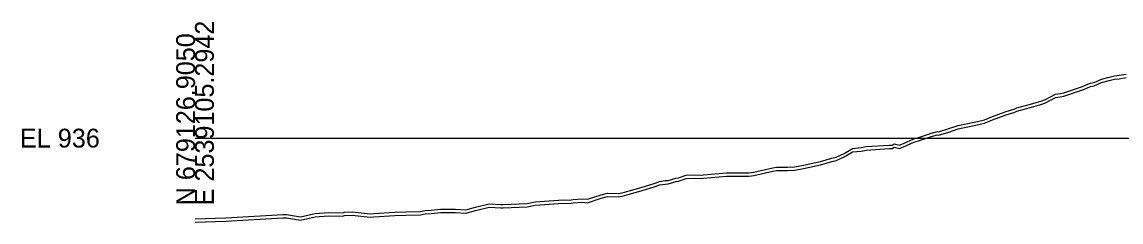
# Model space of a CAD drawing. Extents: x -26 to 2539581, y -16 to 679563.
# Drawn here: x -25.7 to 137.5, y 4987.5 to 5017.3 of the extents above; entities that cross this region are included whole.
import ezdxf

# ---------------------------------------------------------------- set-up
doc = ezdxf.new("R2010")
doc.units = 0
for name, color, linetype in [('DESIGN - SHEET - Light Grid', 7, 'Continuous'), ('SURVEY - GROUND - Bottom of Topsoil Layer', 7, 'Continuous'), ('SURVEY - GROUND - Top of Ground', 7, 'Continuous')]:
    doc.layers.add(name, color=color, linetype=linetype)

msp = doc.modelspace()

# ---------------------------------------------------------------- linework, layer by layer
at = {"layer": 'DESIGN - SHEET - Light Grid'}
msp.add_line((0, 5000), (150, 5000), dxfattribs=at)
at = {"layer": 'SURVEY - GROUND - Bottom of Topsoil Layer'}
for p, q in [((133.52, 5007.79), (134.6, 5008.28)), ((134.6, 5008.28), (135.75, 5008.59)), ((135.75, 5008.59), (136.54, 5008.76)), ((136.54, 5008.76), (137.22, 5008.85)), ((137.22, 5008.85), (138.26, 5009)), ((128.98, 5006.24), (131.76, 5007.18)), ((131.76, 5007.18), (132.08, 5007.31)), ((132.08, 5007.31), (132.96, 5007.68)), ((132.96, 5007.68), (133.52, 5007.79)), ((124.06, 5004.54), (124.52, 5004.7)), ((124.52, 5004.7), (125.57, 5005.02)), ((125.57, 5005.02), (126.27, 5005.23)), ((126.27, 5005.23), (127.02, 5005.67)), ((127.02, 5005.67), (127.74, 5006.04)), ((127.74, 5006.04), (128.43, 5006.14)), ((128.43, 5006.14), (128.98, 5006.24)), ((118.42, 5002.7), (120.27, 5003.41)), ((120.27, 5003.41), (121.73, 5003.88)), ((121.73, 5003.88), (122.04, 5004)), ((122.04, 5004), (123.32, 5004.37)), ((123.32, 5004.37), (124.06, 5004.54)), ((113.33, 5001.36), (113.98, 5001.51)), ((113.98, 5001.51), (116.18, 5001.99)), ((116.18, 5001.99), (117.2, 5002.21)), ((117.2, 5002.21), (118.07, 5002.57)), ((118.07, 5002.57), (118.42, 5002.7)), ((107.4, 4999.58), (109.5, 5000.3)), ((109.5, 5000.3), (110.24, 5000.51)), ((110.24, 5000.51), (110.4, 5000.42)), ((110.4, 5000.42), (111.91, 5000.91)), ((111.91, 5000.91), (113.33, 5001.36)), ((98.88, 4998.08), (99.65, 4998.23)), ((99.65, 4998.23), (103.08, 4998.45)), ((103.08, 4998.45), (103.56, 4998.46)), ((103.56, 4998.46), (103.78, 4998.65)), ((103.78, 4998.65), (104.53, 4998.47)), ((104.53, 4998.47), (105.17, 4998.68)), ((105.17, 4998.68), (106.73, 4999.4)), ((106.73, 4999.4), (107.4, 4999.58)), ((94.57, 4996.54), (95.18, 4996.67)), ((95.18, 4996.67), (96.37, 4997.22)), ((96.37, 4997.22), (97.61, 4997.97)), ((97.61, 4997.97), (98.88, 4998.08)), ((82.95, 4994.43), (85.77, 4995.08)), ((85.77, 4995.08), (86.32, 4995.19)), ((86.32, 4995.19), (87.97, 4995.2)), ((87.97, 4995.2), (88.4, 4995.21)), ((88.4, 4995.21), (88.78, 4995.17)), ((88.78, 4995.17), (90.34, 4995.47)), ((90.34, 4995.47), (92.87, 4996.03)), ((92.87, 4996.03), (94.57, 4996.54)), ((70.24, 4993.2), (71.38, 4993.56)), ((71.38, 4993.56), (71.78, 4993.59)), ((71.78, 4993.59), (72.91, 4993.98)), ((72.91, 4993.98), (74.17, 4994.06)), ((74.17, 4994.06), (75.16, 4994)), ((75.16, 4994), (75.48, 4994.05)), ((75.48, 4994.05), (78.91, 4994.32)), ((78.91, 4994.32), (79.6, 4994.35)), ((79.6, 4994.35), (82.23, 4994.33)), ((82.23, 4994.33), (82.64, 4994.38)), ((82.64, 4994.38), (82.95, 4994.43)), ((63.43, 4991.34), (64.48, 4991.67)), ((64.48, 4991.67), (66.22, 4992.16)), ((66.22, 4992.16), (68.3, 4992.81)), ((68.3, 4992.81), (68.97, 4993.03)), ((68.97, 4993.03), (69.78, 4993.17)), ((69.78, 4993.17), (70.24, 4993.2)), ((49.29, 4989.76), (50.51, 4990.02)), ((50.51, 4990.02), (52.56, 4990.16)), ((52.56, 4990.16), (53.96, 4990.28)), ((53.96, 4990.28), (54.7, 4990.31)), ((54.7, 4990.31), (55.53, 4990.29)), ((55.53, 4990.29), (56.14, 4990.36)), ((56.14, 4990.36), (57.49, 4990.45)), ((57.49, 4990.45), (58.26, 4990.39)), ((58.26, 4990.39), (60.31, 4991.07)), ((60.31, 4991.07), (61.26, 4991.3)), ((61.26, 4991.3), (62.81, 4991.25)), ((62.81, 4991.25), (63.43, 4991.34)), ((17.83, 4988.27), (19.81, 4988.43)), ((19.81, 4988.43), (21.88, 4988.37)), ((21.88, 4988.37), (22.18, 4988.46)), ((22.18, 4988.46), (23.34, 4988.54)), ((23.34, 4988.54), (25.99, 4988.23)), ((26.56, 4988.29), (29.65, 4988.46)), ((29.65, 4988.46), (31.29, 4988.54)), ((31.29, 4988.54), (33.49, 4988.57)), ((33.49, 4988.57), (34.19, 4988.74)), ((34.19, 4988.74), (35.08, 4988.8)), ((35.08, 4988.8), (36.43, 4988.95)), ((36.43, 4988.95), (37.97, 4988.94)), ((37.97, 4988.94), (38.68, 4988.93)), ((38.68, 4988.93), (40.2, 4988.84)), ((40.2, 4988.84), (41.63, 4989.22)), ((41.63, 4989.22), (43.65, 4989.7)), ((43.65, 4989.7), (45.42, 4989.6)), ((45.42, 4989.6), (45.76, 4989.62)), ((45.76, 4989.62), (49.29, 4989.76)), ((0, 4987.5), (4.57, 4987.65)), ((4.57, 4987.65), (13.03, 4988.14)), ((13.03, 4988.14), (13.57, 4988.15)), ((13.57, 4988.15), (15.65, 4987.79)), ((15.65, 4987.79), (17.83, 4988.27)), ((25.99, 4988.23), (26.56, 4988.29))]:
    msp.add_line(p, q, dxfattribs=at)
at = {"layer": 'SURVEY - GROUND - Top of Ground'}
msp.add_lwpolyline([(0, 4988), (4.57, 4988.15), (13.03, 4988.64), (13.57, 4988.65), (15.65, 4988.29), (17.83, 4988.77), (19.81, 4988.93), (21.88, 4988.87), (22.18, 4988.96), (23.34, 4989.04), (25.99, 4988.73), (26.56, 4988.79), (29.65, 4988.96), (31.29, 4989.04), (33.49, 4989.07), (34.19, 4989.24), (35.08, 4989.3), (36.43, 4989.45), (37.97, 4989.44), (38.68, 4989.43), (40.2, 4989.34), (41.63, 4989.72), (43.65, 4990.2), (45.42, 4990.1), (45.76, 4990.12), (49.29, 4990.26), (50.51, 4990.52), (52.56, 4990.66), (53.96, 4990.78), (54.7, 4990.81), (55.53, 4990.79), (56.14, 4990.86), (57.49, 4990.95), (58.26, 4990.89), (60.31, 4991.57), (61.26, 4991.8), (62.81, 4991.75), (63.43, 4991.84), (64.48, 4992.17), (66.22, 4992.66), (68.3, 4993.31), (68.97, 4993.53), (69.78, 4993.67), (70.24, 4993.7), (71.38, 4994.06), (71.78, 4994.09), (72.91, 4994.48), (74.17, 4994.56), (75.16, 4994.5), (75.48, 4994.55), (78.91, 4994.82), (79.6, 4994.85), (82.23, 4994.83), (82.64, 4994.88), (82.95, 4994.93), (85.77, 4995.58), (86.32, 4995.69), (87.97, 4995.7), (88.4, 4995.71), (88.78, 4995.67), (90.34, 4995.97), (92.87, 4996.53), (94.57, 4997.04), (95.18, 4997.17), (96.37, 4997.72), (97.61, 4998.47), (98.88, 4998.58), (99.65, 4998.73), (103.08, 4998.95), (103.56, 4998.96), (103.78, 4999.15), (104.53, 4998.97), (105.17, 4999.18), (106.73, 4999.9), (107.4, 5000.08), (109.5, 5000.8), (110.24, 5001.01), (110.4, 5000.92), (111.91, 5001.41), (113.33, 5001.86), (113.98, 5002.01), (116.18, 5002.49), (117.2, 5002.71), (118.07, 5003.07), (118.42, 5003.2), (120.27, 5003.91), (121.73, 5004.38), (122.04, 5004.5), (123.32, 5004.87), (124.06, 5005.04), (124.52, 5005.2), (125.57, 5005.52), (126.27, 5005.73), (127.02, 5006.17), (127.74, 5006.54), (128.43, 5006.64), (128.98, 5006.74), (131.76, 5007.68), (132.08, 5007.81), (132.96, 5008.18), (133.52, 5008.29), (134.6, 5008.78), (135.75, 5009.09), (136.54, 5009.26), (137.22, 5009.35), (138.26, 5009.5)], dxfattribs=at)

# ---------------------------------------------------------------- texts
at = {"layer": 'DESIGN - SHEET - Light Grid'}
for s, p in [('E 2539105.2942', (2.8, 4990)), ('N 679126.9050', (0, 4990))]:
    msp.add_text(s, height=2.8, rotation=90, dxfattribs=at).set_placement(p)
msp.add_text('EL 936', height=2.8, dxfattribs=at).set_placement((-26, 4998.6))

doc.saveas('drawing.dxf')
